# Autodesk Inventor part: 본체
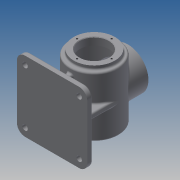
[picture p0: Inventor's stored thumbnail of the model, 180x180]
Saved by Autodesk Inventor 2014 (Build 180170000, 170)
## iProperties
Created: 2015-07
Part Number: 본체
Material: Generic
Document SubType Name: Modeling
Designer: SDA21
Density: 1 g/cm^3
Appearance: Default
Author: SDA21
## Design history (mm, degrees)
sketch "스케치2"
  geometry: L1 (65, -65)-(-65, -65); L2 (-65, -65)-(-65, 65); L3 (-65, 65)-(65, 65); L4 (65, 65)-(65, -65); 3 further points
  constraints: 8 end point, 2 midpoint, 2 parallel, 2 perpendicular, 1 horizontal, 1 horizontal alignment, 1 vertical alignment
  dimensions: "d0" = 130 distance of L3.end L1.start
extrude "돌출1" new body sketch "스케치2" distance "d1" = 10; taper "d2" = 0 deg
node "작업 평면1"
sketch "스케치3"
  geometry: L1 (130, 0)-(0, 0) reference; C1 r 45 at (65, 78); 2 further points
  constraints: 1 centre point, 1 midpoint, 1 vertical alignment
  dimensions: "d4" = 90 diameter of C1; "d5" = 78 distance from line of C1.centre L1
extrude "돌출2" join sketch "스케치3" distance "d6" = 110; taper "d7" = 0 deg
sketch "스케치4"
  geometry: C1 r 45 at (0, 0) reference; C2 r 38 at (0, 0); 1 further point
  constraints: 1 centre point, 1 coincident
  dimensions: "d8" = 76 diameter of C2
extrude "돌출3" join sketch "스케치4" distance "d9" = 7; taper "d10" = 0 deg
node "작업 평면2"
sketch "스케치5"
  geometry: C1 r 38 at (0, 0); 1 further point
  constraints: 1 centre point, 1 coincident
  dimensions: "d12" = 76 diameter of C1
extrude "돌출4" join sketch "스케치5" stored distance "d13" = 7; taper "d14" = 0 deg
sketch "스케치7"
  geometry: L1 (-45, 5)-(45, 5); L2 (45, 5)-(45, -5); L3 (45, -5)-(-45, -5); L4 (-45, -5)-(-45, 5); L5 (-5, 45)-(5, 45); L6 (5, 45)-(5, -45); L7 (5, -45)-(-5, -45); L8 (-5, -45)-(-5, 45); 5 further points
  constraints: 16 end point, 4 midpoint, 4 parallel, 2 horizontal, 2 horizontal alignment, 2 perpendicular, 2 vertical alignment
  dimensions: "d15" = 10 distance of L3.end L1.start; "d16" = 90 distance of L1.start L1.end; "d17" = 10 distance of L5.start L5.end; "d18" = 90 distance of L5.end L6.end
extrude "돌출5" join sketch "스케치7" stored distance "d19" = 7; taper "d20" = 0 deg
sketch "스케치8"
  geometry: C1 r 38 at (0, 0) reference; C2 r 27 at (0, 0); 1 further point
  constraints: 1 centre point, 1 coincident
  dimensions: "d21" = 54 diameter of C2
extrude "돌출6" cut sketch "스케치8" distance "d22" = 14; taper "d23" = 0 deg
sketch "스케치9"
  geometry: C1 r 27 at (0, 0) reference; C2 r 40 at (0, 0); 1 further point
  constraints: 1 centre point, 1 coincident
  dimensions: "d24" = 80 diameter of C2
extrude "돌출7" cut sketch "스케치9" distance "d25" = 96; taper "d26" = 0 deg
sketch "스케치10"
  geometry: C1 r 38 at (0, 0) reference; C2 r 27 at (0, 0)
  constraints: 1 centre point, 1 coincident
  dimensions: "d27" = 54 diameter of C2
extrude "돌출8" cut sketch "스케치10" stored distance "d28" = 96; taper "d29" = 0 deg
sketch "스케치11" dims "d30" = 64
  geometry: C1 r 27 at (0, 0) reference; C2 r 38 at (0, 0) reference; 2 further points
  constraints: 2 vertical alignment, 1 coincident, 2 other
hole "구멍1" sketch "스케치11" at (0, 32) diameter "d31" = 3.242; stored, may be unused: countersink angle "d35" = 90 deg, drill point angle "d37" = 118 deg; dims "d32" = 8, "d33" = 4, "d34" = 2, "d36" = 10
sketch "스케치12" dims "d41" = 64
  geometry: C1 r 38 at (0, 0) reference; 3 further points
  constraints: 2 vertical alignment, 1 coincident, 2 other
hole "구멍2" sketch "스케치12" at (0, 32) diameter "d42" = 3.242; stored, may be unused: countersink angle "d46" = 90 deg, drill point angle "d48" = 118 deg; dims "d43" = 8, "d44" = 4, "d45" = 2, "d47" = 10
sketch "스케치13"
  geometry: C1 r 45 at (0, 0) reference; 2 further points
  constraints: 2 coincident, 1 other
feature "엠보싱1" sketch "스케치13" dims "d0" = 130, "d52" = 0.5, "d53" = 0
fillet "모깎기1" dims "d54" = 15
sketch "스케치15"
  geometry: C1 r 7.5 at (-50, 50); C2 r 7.5 at (50, 50); C3 r 7.5 at (-50, -50); C4 r 7.5 at (50, -50); A1 r 15 centre (-50, 50) between (-50, 65) and (-65, 50) reference; A2 r 15 centre (-50, -50) between (-65, -50) and (-50, -65) reference; A3 r 15 centre (50, -50) between (50, -65) and (65, -50) reference; A4 r 15 centre (50, 50) between (65, 50) and (50, 65) reference; 1 further point
  constraints: 4 centre point, 4 coincident
  dimensions: "d55" = 15 diameter of C1; "d56" = 15 diameter of C2; "d57" = 15 diameter of C3; "d58" = 15 diameter of C4
extrude "돌출9" join sketch "스케치15" distance "d59" = 3; taper "d60" = 0 deg
sketch "스케치16"
  geometry: C1 r 5 at (-50, 50); C2 r 5 at (50, 50); C3 r 5 at (-50, -50); C4 r 5 at (50, -50); A1 r 15 centre (-50, -50) between (-65, -50) and (-50, -65) reference; A2 r 15 centre (50, -50) between (50, -65) and (65, -50) reference; A3 r 15 centre (50, 50) between (65, 50) and (50, 65) reference; A4 r 15 centre (-50, 50) between (-50, 65) and (-65, 50) reference; 1 further point
  constraints: 4 centre point, 4 coincident
  dimensions: "d61" = 10 diameter of C1; "d62" = 10 diameter of C2; "d63" = 10 diameter of C3; "d64" = 10 diameter of C4
extrude "돌출10" cut sketch "스케치16" stored distance "d65" = 3; taper "d66" = 0 deg
chamfer "모따기1" distance "d67" = 1; stored, may be unused: second distance "d68" = 2, angle "d69" = 45 deg
chamfer "모따기2" distance "d70" = 1; stored, may be unused: second distance "d71" = 2, angle "d72" = 45 deg
fillet "모깎기2" dims "d73" = 3
fillet "모깎기3" dims "d74" = 3
fillet "모깎기4" dims "d75" = 3
fillet "모깎기5" dims "d76" = 3
node "솔리드1"
pattern_circular "원형 패턴1" dims angle "d39" = 360 deg
pattern_circular "원형 패턴2" dims angle "d50" = 360 deg
